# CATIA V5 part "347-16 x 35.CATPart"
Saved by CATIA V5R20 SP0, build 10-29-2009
Part number: 347-16 x 35
Definition: NONE
Nomenclature: 347-16 x 35
Source: Unknown
Description: 347-16 x 35
Bounding box of the stored display mesh (mm): x 0 to 35, y -13 to 13, z -13 to 13
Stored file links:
  C:\Users\Utente\Desktop\IO LAVORO\3D X SITO CF\X SITO\3D files 347\347-16 x 35.CATPart
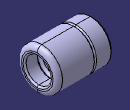
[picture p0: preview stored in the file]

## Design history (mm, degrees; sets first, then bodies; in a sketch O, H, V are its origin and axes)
Body1 "347-16 x 35" (main body)
  Solid1: solid without history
